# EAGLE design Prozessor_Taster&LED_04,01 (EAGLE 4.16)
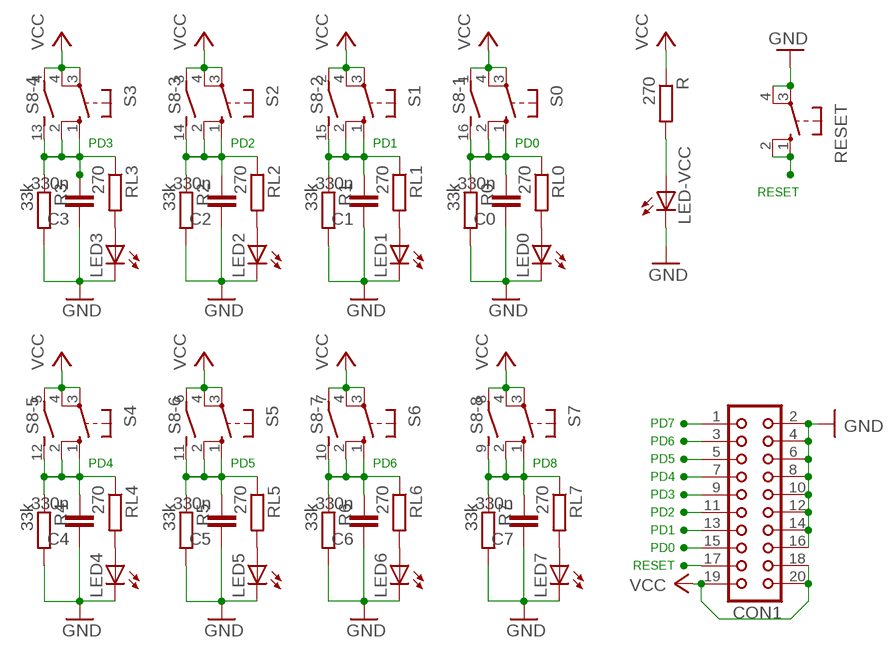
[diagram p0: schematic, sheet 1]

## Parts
C0  330n  C-EU050-030X075  [C050-030X075]
C1  330n  C-EU050-030X075  [C050-030X075]
C2  330n  C-EU050-030X075  [C050-030X075]
C3  330n  C-EU050-030X075  [C050-030X075]
C4  330n  C-EU050-030X075  [C050-030X075]
C5  330n  C-EU050-030X075  [C050-030X075]
C6  330n  C-EU050-030X075  [C050-030X075]
C7  330n  C-EU050-030X075  [C050-030X075]
CON1  CON20  [CON20]
LED0  LED3MM  [LED3MM]
LED1  LED3MM  [LED3MM]
LED2  LED3MM  [LED3MM]
LED3  LED3MM  [LED3MM]
LED4  LED3MM  [LED3MM]
LED5  LED3MM  [LED3MM]
LED6  LED3MM  [LED3MM]
LED7  LED3MM  [LED3MM]
LED-VCC  LED3MM  [LED3MM]
R  270  R-EU_0207/10  [0207/10]
R0  33k  R-EU_0204/7  [0204/7]
R1  33k  R-EU_0204/7  [0204/7]
R2  33k  R-EU_0204/7  [0204/7]
R3  33k  R-EU_0204/7  [0204/7]
R4  33k  R-EU_0204/7  [0204/7]
R5  33k  R-EU_0204/7  [0204/7]
R6  33k  R-EU_0204/7  [0204/7]
R7  33k  R-EU_0204/7  [0204/7]
RESET  10-XX  [B3F-10XX]
RL0  270  R-EU_0204/7  [0204/7]
RL1  270  R-EU_0204/7  [0204/7]
RL2  270  R-EU_0204/7  [0204/7]
RL3  270  R-EU_0204/7  [0204/7]
RL4  270  R-EU_0204/7  [0204/7]
RL5  270  R-EU_0204/7  [0204/7]
RL6  270  R-EU_0204/7  [0204/7]
RL7  270  R-EU_0204/7  [0204/7]
S0  10-XX  [B3F-10XX]
S1  10-XX  [B3F-10XX]
S2  10-XX  [B3F-10XX]
S3  10-XX  [B3F-10XX]
S4  10-XX  [B3F-10XX]
S5  10-XX  [B3F-10XX]
S6  10-XX  [B3F-10XX]
S7  10-XX  [B3F-10XX]
S8  DIP08S  [DIP08S]

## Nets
GND: C0.1 C1.1 C2.1 C3.1 C4.1 C5.1 C6.1 C7.1 CON1.2 CON1.4 CON1.6 CON1.8 CON1.10 CON1.12 CON1.14 CON1.16 LED0.K(C) LED1.K(C) LED2.K(C) LED3.K(C) LED4.K(C) LED5.K(C) LED6.K(C) LED7.K(C) LED-VCC.K(C) R0.2 R1.2 R2.2 R3.2 R4.2 R5.2 R6.2 R7.2 RESET.3(P) RESET.4(P1)
N$3: LED3.A RL3.2
N$4: LED2.A RL2.2
N$5: LED1.A RL1.2
N$6: LED0.A RL0.2
N$7: LED7.A RL7.2
N$8: LED6.A RL6.2
N$9: LED5.A RL5.2
N$10: LED4.A RL4.2
N$16: LED-VCC.A R.2
PD0: C0.2 CON1.15 R0.1 RL0.1 S0.1(S) S0.2(S1) S8.16
PD1: C1.2 CON1.13 R1.1 RL1.1 S1.1(S) S1.2(S1) S8.15
PD2: C2.2 CON1.11 R2.1 RL2.1 S2.1(S) S2.2(S1) S8.14
PD3: C3.2 CON1.9 R3.1 RL3.1 S3.1(S) S3.2(S1) S8.13
PD4: C4.2 CON1.7 R4.1 RL4.1 S4.1(S) S4.2(S1) S8.12
PD5: C5.2 CON1.5 R5.1 RL5.1 S5.1(S) S5.2(S1) S8.11
PD6: C6.2 CON1.3 R6.1 RL6.1 S6.1(S) S6.2(S1) S8.10
PD7: C7.2 CON1.1 R7.1 RL7.1 S7.1(S) S7.2(S1) S8.9
RESET: CON1.17 RESET.1(S) RESET.2(S1)
VCC: CON1.18 CON1.19 CON1.20 R.1 S0.3(P) S0.4(P1) S1.3(P) S1.4(P1) S2.3(P) S2.4(P1) S3.3(P) S3.4(P1) S4.3(P) S4.4(P1) S5.3(P) S5.4(P1) S6.3(P) S6.4(P1) S7.3(P) S7.4(P1) S8.1 S8.2 S8.3 S8.4 S8.5 S8.6 S8.7 S8.8

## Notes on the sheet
- PD3 | PD2 | PD1 | PD0
- RESET
- PD7
- PD6
- PD5
- PD4 | PD5 | PD6 | PD8
- PD4
- PD3
- PD2
- PD1
- PD0
- RESET

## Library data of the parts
C0 C1-C7 = rcl:C-EU: CAPACITOR, European symbol
CON1 = con-harting:CON20: CONNECTOR
LED0 LED1-LED7 LED-VCC = led:LED: LED
R R0 R1-R7 RL0 RL1-RL7 = rcl:R-EU_: RESISTOR, European symbol
RESET S0 S1-S7 = switch-omron:10-XX: OMRON SWITCH
S8 = switch-dil:DIP08S: DIL/CODE SWITCH

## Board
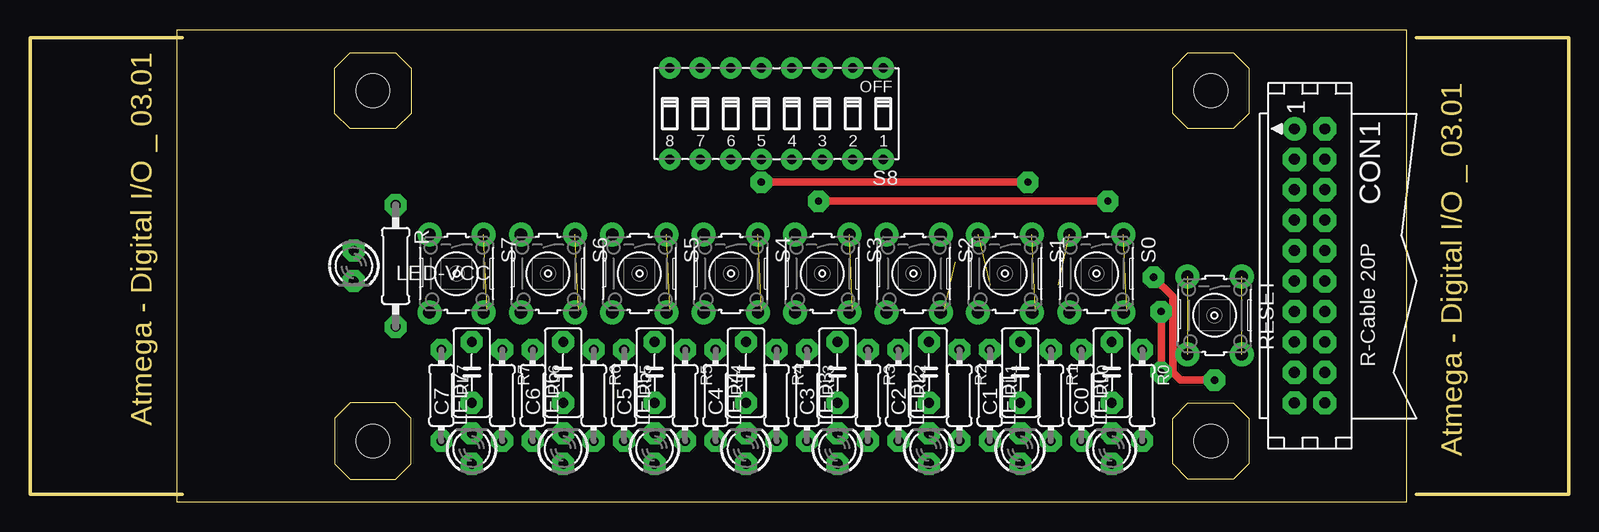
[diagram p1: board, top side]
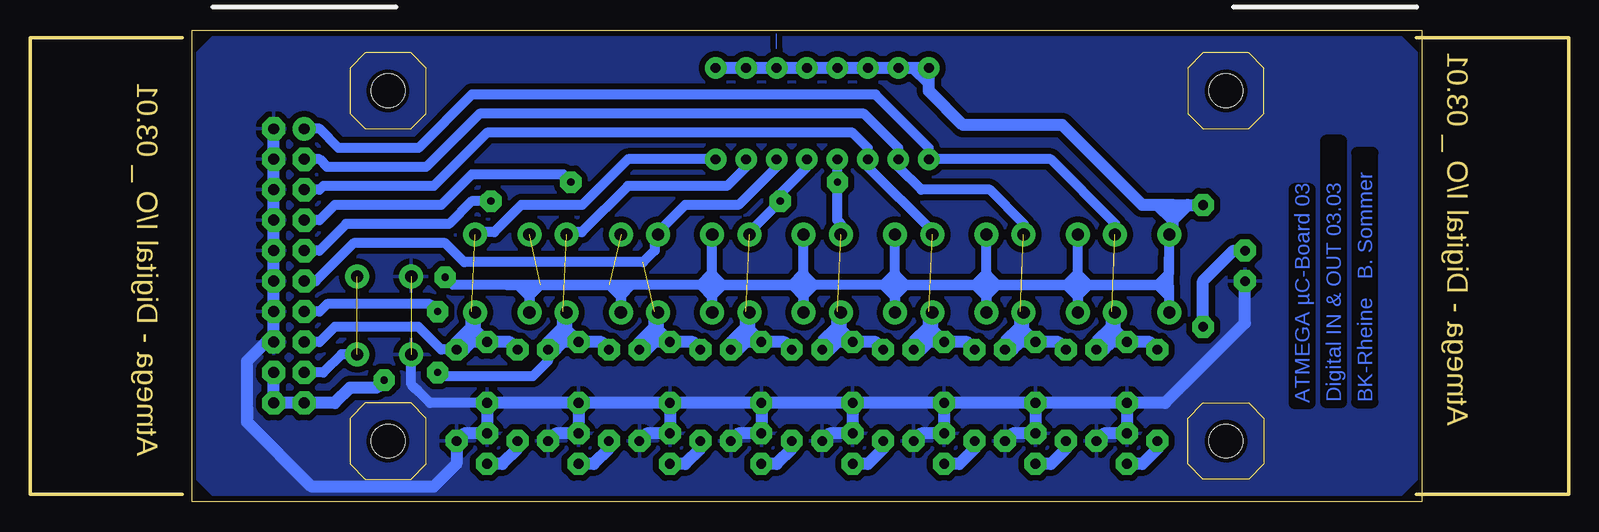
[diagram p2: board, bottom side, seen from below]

Size 128.27 x 39.36 mm. Coordinates in mm from the lower left corner, seen from the top.
Outline: 12.7,38.73 0,38.73 0,0.63 12.7,0.63
Outline: 115.57,38.73 128.27,38.73 128.27,0.63 115.57,0.63
Outline: 12.23,0 114.77,0 114.77,39.36 12.23,39.36 12.23,0
Outline: 96.52,37.46 100.33,37.46 101.6,36.19 101.6,32.38 100.33,31.11 96.52,31.11 95.25,32.38 95.25,36.19 96.52,37.46
Outline: 26.67,37.46 30.48,37.46 31.75,36.19 31.75,32.38 30.48,31.11 26.67,31.11 25.4,32.38 25.4,36.19 26.67,37.46
Outline: 100.33,8.25 101.6,6.98 101.6,3.17 100.33,1.9 96.52,1.9 95.25,3.17 95.25,6.98 96.52,8.25 100.33,8.25
Outline: 30.48,8.25 26.67,8.25 25.4,6.98 25.4,3.17 26.67,1.9 30.48,1.9 31.75,3.17 31.75,6.98 30.48,8.25
Copper layers (1*16): Top 0.035mm / dielectric 1.5mm / Bottom 0.035mm
Design rules "sommer_01": minimum track width 24mil, minimum drill 0.5mm, track to track 20mil, track to pad 23mil, pad to pad 23mil, via to via 24mil, smd to smd 8mil, copper to edge 0mil, drill to drill 8mil, minimum pad ring 20mil, minimum via ring 20mil, stop-mask expansion 4mil, vias tented up to drill 0mil, thermal gap 20mil
Holes 2.8 mm at 98.42,34.29 28.57,34.29 98.42,5.08 28.57,5.08

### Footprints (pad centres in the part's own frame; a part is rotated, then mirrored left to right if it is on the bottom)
C050-030X075 = drill 0.813 pad 1.778 octagon: 1 -2.54,0; 2 2.54,0
CON20 = drill 0.914 round: 1 -11.43,-1.27 | drill 0.914 octagon: 2 -11.43,1.27; 3 -8.89,-1.27; 4 -8.89,1.27; 5 -6.35,-1.27; 6 -6.35,1.27; 7 -3.81,-1.27; 8 -3.81,1.27; 9 -1.27,-1.27; 10 -1.27,1.27; 11 1.27,-1.27; 12 1.27,1.27; 13 3.81,-1.27; 14 3.81,1.27; 15 6.35,-1.27; 16 6.35,1.27; 17 8.89,-1.27; 18 8.89,1.27; 19 11.43,-1.27; 20 11.43,1.27
LED3MM = drill 0.813 pad 1.778 octagon: A -1.27,0; K 1.27,0
0207/10 = drill 0.813 pad 1.778 octagon: 1 -5.08,0; 2 5.08,0
0204/7 = drill 0.813 pad 1.778 octagon: 1 -3.81,0; 2 3.81,0
B3F-10XX = drill 1.016 long: 1 -3.251,2.261; 2 3.251,2.261; 3 -3.251,-2.261; 4 3.251,-2.261
DIP08S = drill 0.813 long: 1 -8.89,-3.81; 2 -6.35,-3.81; 3 -3.81,-3.81; 4 -1.27,-3.81; 5 1.27,-3.81; 6 3.81,-3.81; 7 6.35,-3.81; 8 8.89,-3.81; 9 8.89,3.81; 10 6.35,3.81; 11 3.81,3.81; 12 1.27,3.81; 13 -1.27,3.81; 14 -3.81,3.81; 15 -6.35,3.81; 16 -8.89,3.81

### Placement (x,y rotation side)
C0  90.17,10.79 90 top
C1  82.55,10.79 90 top
C2  74.93,10.79 90 top
C3  67.31,10.79 90 top
C4  59.69,10.79 90 top
C5  52.07,10.79 90 top
C6  44.45,10.79 90 top
C7  36.83,10.79 90 top
CON1  106.68,19.68 270 top
LED0  90.17,4.44 90 top
LED1  82.55,4.44 90 top
LED2  74.93,4.44 90 top
LED3  67.31,4.44 90 top
LED4  59.69,4.44 90 top
LED5  52.07,4.44 90 top
LED6  44.45,4.44 90 top
LED7  36.83,4.44 90 top
LED-VCC  26.99,19.68 270 top
R  30.48,19.68 270 top
R0  92.71,8.89 270 top
R1  85.09,8.89 270 top
R2  77.47,8.89 270 top
R3  69.85,8.89 270 top
R4  62.23,8.89 270 top
R5  54.61,8.89 270 top
R6  46.99,8.89 270 top
R7  39.37,8.89 270 top
RESET  98.74,15.55 270 top
RL0  87.63,8.89 270 top
RL1  80.01,8.89 270 top
RL2  72.39,8.89 270 top
RL3  64.77,8.89 270 top
RL4  57.15,8.89 270 top
RL5  49.53,8.89 270 top
RL6  41.91,8.89 270 top
RL7  34.29,8.89 270 top
S0  88.9,19.04 270 top
S1  81.28,19.04 270 top
S2  73.66,19.04 270 top
S3  66.04,19.04 270 top
S4  58.42,19.04 270 top
S5  50.8,19.04 270 top
S6  43.18,19.04 270 top
S7  35.56,19.04 270 top
S8  62.23,32.38 180 top

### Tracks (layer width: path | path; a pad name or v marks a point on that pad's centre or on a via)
GND  (1 unrouted)
  Bottom 0.813: C0.1 94.93,8.25 95.89,9.2 | 95.89,9.2 96.2,9.52 | RESET.4 96.48,9.8 95.89,9.2
  Bottom 1.016: 110.17,7.93 110.17,7.3 | 110.17,7.93 110.17,11.74 108.59,13.33 108.27,13.33 107.95,13.01 CON1.16 CON1.14 CON1.12 CON1.10 CON1.8 CON1.6 CON1.4 CON1.2 | C7.1 LED7.K 38.73,5.71 R7.2 | R6.2 46.36,5.71 LED6.K C6.1 | C1.1 C0.1 LED0.K 92.08,5.71 R0.2 92.71,3.17 94.62,1.27 104.78,1.27 110.17,6.66 110.17,7.93 | C2.1 C1.1 | C3.1 C2.1 | C4.1 C3.1 | C5.1 C4.1 | C6.1 C5.1 | C7.1 C6.1 | C5.1 LED5.K 53.97,5.71 R5.2 | C4.1 LED4.K 61.59,5.71 R4.2 | C3.1 LED3.K 69.22,5.71 R3.2 | C2.1 LED2.K 76.84,5.71 R2.2 | C1.1 LED1.K 84.45,5.71 R1.2 | 110.17,7.93 110.17,6.98 | C7.1 33.66,8.25 26.99,14.92 LED-VCC.K
  pour Bottom: 12.7,37.46 13.97,38.73 113.03,38.73 114.3,37.46 114.3,1.9 113.03,0.63 13.97,0.63 12.7,1.9
N$1  (via drill 0.5 pad 2.54)
  other vias: 28.57,34.29
N$2  (via drill 0.6 pad 2.54)
  other vias: 28.57,5.08
N$3
  Bottom 1.016: RL3.2 64.77,4.44 66.04,3.17 LED3.A
N$4
  Bottom 1.016: RL2.2 72.39,4.44 73.66,3.17 LED2.A
N$5
  Bottom 1.016: RL1.2 80.01,4.44 81.28,3.17 LED1.A
N$6
  Bottom 1.016: RL0.2 87.63,4.44 88.9,3.17 LED0.A
N$7
  Bottom 1.016: RL7.2 34.29,4.44 35.56,3.17 LED7.A
N$8
  Bottom 1.016: RL6.2 41.91,4.44 43.18,3.17 LED6.A
N$9
  Bottom 1.016: RL5.2 49.53,4.44 50.8,3.17 LED5.A
N$10
  Bottom 1.016: RL4.2 57.15,4.44 58.42,3.17 LED4.A
N$11
  Bottom 0: 66.04,37.78 66.04,39.05
N$12  (via drill 0.5 pad 2.54)
  other vias: 98.42,34.29
N$13  (via drill 0.6 pad 2.54)
  other vias: 98.42,5.08
N$15
  pour Bottom: 13.97,37.46 113.03,37.46 113.03,1.9 13.97,1.9
N$16
  Bottom 1.016: R.2 30.48,18.41 27.94,20.95 LED-VCC.A
PD0  (1 unrouted)
  Bottom 0.813: S8.16 78.42,28.57 82.23,24.76 87.31,24.76 89.57,22.5 91.16,22.5 S0.1 | CON1.15 104.14,13.33 102.87,14.6 95.89,14.6 93.98,12.7 R0.1
  Bottom 1.016: S0.2 91.16,14.32 C0.2 | RL0.1 88.27,13.33 C0.2 | R0.1 92.08,12.7 91.44,13.33 | C0.2 91.44,13.33 | 91.44,13.33 91.44,14.6 | 91.44,14.6 91.44,15.87 | 91.44,13.33 92.71,13.33 91.44,14.6
PD1  (via drill 0.6 pad 1.78)  (1 unrouted)
  Top 0.61: v94.3,10.79 v94.3,15.87
  Bottom 0.813: S8.15 68.58,27.93 70.17,26.35 78.42,26.35 82.27,22.5 83.54,22.5 S1.1 | v94.3,15.87 94.93,16.5 103.51,16.5 104.14,15.87 CON1.13 | v94.3,10.79 93.98,10.47 86.36,10.47 85.09,11.74 R1.1
  Bottom 1.016: S1.2 83.54,14.32 C1.2 | RL1.1 80.64,13.33 C1.2 | R1.1 84.45,12.7 83.82,13.33 | C1.2 83.82,13.33 | 83.82,13.33 83.82,14.6 | 83.82,14.6 83.82,15.87 | 83.82,14.6 85.09,13.33
PD2  (1 unrouted)
  Bottom 0.813: CON1.11 104.46,18.41 101.28,21.58 93.66,21.58 92.08,20 77.15,20 76.2,20.95 76.2,22.22 76.12,22.3 S2.1 75.92,22.5 73.66,24.76 69.22,24.76 66.04,27.93 S8.14
  Bottom 1.016: S2.2 75.92,14.32 C2.2 | RL2.1 73.03,13.33 C2.2 | R2.1 76.84,12.7 76.2,13.33 | C2.2 76.2,13.33 | 76.2,13.33 76.2,14.6 | 76.2,14.6 76.2,15.87 | 76.2,14.6 77.47,13.33
PD3  (via drill 0.6 pad 1.78)  (1 unrouted)
  Top 0.61: v65.72,25.08 v89.85,25.08
  Bottom 0.813: CON1.9 104.14,20.95 101.92,23.17 93.34,23.17 91.44,25.08 v89.85,25.08 | S8.13 63.5,27.93 65.72,25.71 v65.72,25.08 68.3,22.5 S3.1
  Bottom 1.016: S3.2 68.3,14.32 C3.2 | RL3.1 65.41,13.33 C3.2 | R3.1 69.22,12.7 68.58,13.33 | C3.2 68.58,13.33 | 68.58,13.33 68.58,14.6 | 68.58,14.6 68.58,15.87 | 68.58,14.6 69.85,13.33
PD4  (via drill 0.6 pad 1.78)  (1 unrouted)
  Top 0.61: v60.96,26.66 v83.19,26.66
  Bottom 0.813: S4.1 60.68,23.21 60.96,23.49 v60.96,26.66 S8.12 | CON1.7 104.14,23.49 102.87,24.76 93.98,24.76 91.44,27.3 83.82,27.3 v83.19,26.66
  Bottom 1.016: S4.2 60.68,14.32 C4.2 | RL4.1 57.78,13.33 C4.2 | R4.1 61.59,12.7 60.96,13.33 | C4.2 60.96,13.33 | 60.96,13.33 60.96,14.6 | 60.96,14.6 60.96,15.87 | 60.96,14.6 62.23,13.33
PD5  (1 unrouted)
  Bottom 0.813: S5.1 53.06,22.58 58.42,27.93 S8.11 58.42,29.52 59.69,30.79 90.17,30.79 94.62,26.35 103.82,26.35 104.14,26.03 CON1.5
  Bottom 1.016: S5.2 53.06,14.32 C5.2 | RL5.1 50.17,13.33 C5.2 | R5.1 53.97,12.7 53.34,13.33 | C5.2 53.34,13.33 | 53.34,13.33 53.34,14.6 | 53.34,14.6 53.34,15.87 | 53.34,14.6 54.61,13.33
PD6  (1 unrouted)
  Bottom 0.813: S6.1 45.44,23.21 48.26,26.03 53.97,26.03 55.88,27.93 S8.10 55.88,29.52 58.74,32.38 90.81,32.38 95.25,27.93 103.51,27.93 104.14,28.57 CON1.3
  Bottom 1.016: S6.2 45.44,14.32 C6.2 | RL6.1 42.55,13.33 C6.2 | R6.1 46.36,12.7 45.72,13.33 | C6.2 45.72,13.33 | 45.72,13.33 45.72,14.6 | 45.72,14.6 45.72,15.87 | 45.72,14.6 46.99,13.33
PD7  (1 unrouted)
  Bottom 0.813: S7.1 37.82,23.21 43.18,28.57 S8.9 53.34,29.52 57.78,33.97 91.44,33.97 95.89,29.52 102.55,29.52 104.14,31.11 CON1.1
  Bottom 1.016: S7.2 37.82,14.32 C7.2 | R7.1 38.73,12.7 38.1,13.33 | C7.2 38.1,13.33 | RL7.1 34.92,13.33 C7.2 | 38.1,13.33 38.1,14.6 | 38.1,14.6 38.1,15.87 | 38.1,14.6 39.37,13.33
RESET  (1 unrouted)
  Bottom 0.813: RESET.2 102.31,12.3 103.82,10.79 CON1.17
VCC  (via drill 0.6 pad 1.78)  (2 unrouted)
  Top 0.61: v98.74,10.16 95.89,10.16 95.25,10.79 95.25,17.14 v93.66,18.73
  Bottom 0.813: S7.4 33.3,17.1 34.29,18.09 | 41.91,18.09 40.92,17.1 S6.4 40.92,17.18 40,18.09 | 49.53,18.09 48.54,17.1 S5.4 48.54,17.18 47.62,18.09 | 57.15,18.09 56.16,17.1 S4.4 56.16,17.18 55.25,18.09 | 64.77,18.09 63.78,17.1 S3.4 63.78,17.18 62.86,18.09 | 72.39,18.09 71.4,17.1 S2.4 71.4,17.18 70.48,18.09 | 34.29,18.09 40,18.09 | 47.62,18.09 41.91,18.09 | 55.25,18.09 49.53,18.09 | 57.15,18.09 62.86,18.09 | 70.48,18.09 64.77,18.09 | 72.39,18.09 78.11,18.09 79.02,17.18 S1.4 79.02,17.1 80.01,18.09 85.73,18.09 86.64,17.18 S0.4 86.64,17.1 87.63,18.09 88.58,18.09 | 88.58,18.09 93.03,18.09 v93.66,18.73 | S7.3 33.3,19.08 34.29,18.09 | S6.3 40.92,19.08 40.96,19.04 | 40.96,19.04 41.91,18.09 | S5.3 48.54,19.08 48.58,19.04 | 48.58,19.04 49.53,18.09 | S4.3 56.16,19.08 56.2,19.04 | 56.2,19.04 57.15,18.09 | S3.3 63.78,19.08 63.82,19.04 | 63.82,19.04 64.77,18.09 | S2.3 71.4,19.08 71.44,19.04 | 71.44,19.04 72.39,18.09 | 70.48,18.09 88.58,18.09 | 62.86,18.09 70.48,18.09 | 55.56,18.09 62.86,18.09 | 55.25,18.09 55.56,18.09 | 47.62,18.09 55.25,18.09 | 40,18.09 47.62,18.09 | 40,18.09 33.34,18.09 | 33.34,18.09 33.34,20.31 | 33.34,18.09 33.34,16.19 | 40,18.09 40.96,19.04 | 47.62,18.09 48.58,19.04 | 55.56,18.09 55.56,18.41 56.2,19.04 | 55.25,18.09 56.2,19.04 | 62.86,18.09 63.82,19.04 | 70.48,18.09 71.44,19.04
  Bottom 1.016: CON1.18 CON1.20 CON1.19 102.87,8.25 101.6,9.52 99.38,9.52 v98.74,10.16 | S8.1 S8.2 S8.3 S8.4 S8.5 S8.6 S8.7 54.61,36.19 | 53.34,34.92 53.34,34.29 50.48,31.43 42.23,31.43 35.56,24.76 34.29,24.76 | 53.34,34.92 S8.8 54.61,36.19 | 33.02,24.76 31.75,24.76 | 31.75,24.76 R.1 | 33.02,24.76 34.29,24.76 | S7.3 33.02,22.58 33.02,23.49 | 33.02,23.49 33.02,24.76 | 33.02,23.49 31.75,24.76 | 33.02,23.49 34.29,24.76 | 53.34,34.92 54.61,36.19

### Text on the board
Bottom: BK-Rheine B. Sommer | Digital IN & OUT 03.03 | ATMEGA µC-Board 03
Dimension: Atmega - Digital I/O _ 03.01 | Atmega - Digital I/O _ 03.01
